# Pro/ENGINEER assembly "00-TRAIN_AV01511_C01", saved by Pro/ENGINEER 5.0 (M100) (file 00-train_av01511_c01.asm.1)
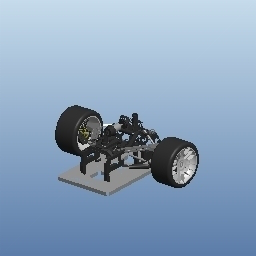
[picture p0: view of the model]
Units: millimeter Newton Second (mmNs); MM, TONNE, HOURS

Other components: CHASSIS-AV_01509-V11_C01, 1_SUP_TRAIN-AV_C01, Y158_1-2-RENVOI_SERVO_C01, BASCULEUR_V0_1_C01, 80460500-AMORT_COURT_STD, 80657401-TRIANGLE_AVANT_SUP_C01, TRIANGLE-INF-AV-D_C01, FUSEE-AV_DROITE_C01, 80651701-TIRANT_DIRECT_AV_C01, 80653001-TIRANT_BASC_AV_C01, 80657401-TRIANGLE_AVANT_SUP_C01, TRIANGLE-INF-AV-G_C01, 80653001-TIRANT_BASC_AV_C01, 80651701-TIRANT_DIRECT_AV_C01, FUSEE-AV_GAUCHE_C01

Other named items: A-DROITE, A-DESSUS, A-FACE, A-R0, S1, S2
